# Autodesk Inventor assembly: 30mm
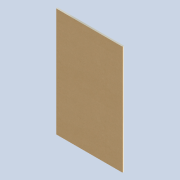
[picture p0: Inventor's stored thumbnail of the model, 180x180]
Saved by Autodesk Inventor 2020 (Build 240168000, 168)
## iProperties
Created: 2020-11
Part Number: 30mm
Document SubType Name: Assembly
Designer: Yolande
Author: Yolande
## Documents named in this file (2)
- D:\Drawing Division\3. Revit Family Files\2. Kraft\30mm.iam
- D:\Drawing Division\3. Revit Family Files\2. Kraft\Lambdaboard 30mm Kraft.ipt
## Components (1 placed, 1 different names)
1. Lambdaboard 30mm Kraft:1
